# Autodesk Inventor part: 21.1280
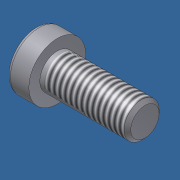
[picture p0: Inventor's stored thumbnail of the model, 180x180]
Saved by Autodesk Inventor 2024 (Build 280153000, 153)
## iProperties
Created: 2006-02
Part Number: 21.1280
Material: Steel, Mild
Description: M8X22 SHCS
Document SubType Name: Modeling
Standard: DIN 7984
Designer: Andy Moles
Standards Organization: DIN
Language: en-US
Size Designation: M8 x 20
Categories: <MemberInstance><Categories><Category DisplayName="Fasteners" InternalName="e4da775c-781d-43d5-af7c-5136215cf5a6" Mnemonic="FSTN"><Category DisplayName="Bolts"
Density: 7.85 g/cm^3
Mass: 13.0366 g
Surface Area: 10.6794 cm^2
Volume: 1.66071 cm^3
Vendor: S
Appearance: Zinc
Author: Andy Moles
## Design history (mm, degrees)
body "Solid1"
workplane "Work Plane1"
revolve "Body" stored, may be unused: angle "d10" = 90 deg
sketch "Sketch2"
  geometry: L1 (0, -7.8)-(0, 10.4) reference; L2 (-7.8, 0)-(10.4, 0) reference; L3 (2.887, 0)-(1.443, -2.5); L4 (1.443, -2.5)-(-1.443, -2.5); L5 (-1.443, -2.5)-(-2.887, 0); L6 (-2.887, 0)-(-1.443, 2.5); L7 (-1.443, 2.5)-(1.443, 2.5); L8 (1.443, 2.5)-(2.887, 0); 2 further points
  constraints: 12 end point, 1 coincident, 1 horizontal alignment, 1 point on line, 12 other
extrude "Slot" join sketch "Sketch2" stored distance "d11" = 10; taper "d12" = 0 deg
fillet "Fillet1" dims "d17" = 0.8 (= RR)
feature "Thread" dims "d13" = 22, "d14" = 0
chamfer "Chamfer1" distance "d15" = 0.76681 (= -0.5 x SPD + 0.5 x GD); stored, may be unused: second distance "d16" = 0.76681 (= GUL), angle "d27" = 45 deg
sketch "Sketch1"
  geometry: L1 (0.467, 0)-(22, 0); L2 (22, 0)-(22, 4); L3 (22, 4)-(1, 4); L4 (1, 4)-(0.233, 4); L5 (0.233, 4)-(0, 4); L6 (0, 4)-(0, 6.5); L7 (0, 6.5)-(-5, 6.5); L8 (-5, 6.5)-(-5, 2.887); L9 (-5, 2.887)-(-1.2, 2.887); L10 (-1.2, 2.887)-(0.467, 0); L11 (-7.5, 0)-(27.5, 0) reference; L12 (0, -0.65)-(0, 8.45) reference; L13 (1, 4)-(0, 4)
  constraints: 22 end point, 6 parallel, 2 collinear, 2 perpendicular, 1 horizontal, 1 point on line
  dimensions: "d1" = 21 distance from line of L3.end L2 (= GEL); "d2" = 0.76691 distance of L4.end L3.end (computed from GAL); "d3" = 5 distance between parallel lines of L8 L6 (= KOH); "d4" = 3.8 distance of L8.end L9.end (= INTI); "d5" = 60 deg angle of L10 L1; "d6" = 8 diameter of L3 L1 (= GD); "d7" = 8 diameter of L5 L1 (= BDM); "d8" = 5.7735 diameter of L9 L1 (= 1.1547 x SW); "d9" = 13 diameter of L7 L1 (= KOD); "d26" = 22 distance between parallel lines of L12 L2 (= NLG)
other parameters: "GD" = 8 (= NND) [user parameter; used in 2 equation terms], "NLG" = 22 [user parameter; used in 1 equation term], "GEL" = 21 [user parameter; used in 1 equation term], "KOD" = 13 [user parameter; used in 1 equation term], "KOH" = 5 [user parameter; used in 1 equation term], "INTI" = 3.8 [user parameter; used in 1 equation term], "GAL" = 0.76681 (= 0.61345 x PTC) [user parameter; used in 1 equation term], "GUL" = 0.76681 (= 0.61345 x PTC) [user parameter; used in 1 equation term], "BDM" = 8 (= NND) [user parameter; used in 1 equation term], "SW" = 5 [user parameter; used in 2 equation terms], "RR" = 0.8 [user parameter; used in 1 equation term], "SPD" = 6.46637 (= NND - 1.2269 x PTC) [user parameter; used in 1 equation term], "d19" = 0, "d28" = 0, "d29" = 0, "TOA" = 30 deg [user parameter], "GD1" = 6.46637 (= THREADDIA - 1.2269 x PTC) [user parameter], "THREADDIA" = 8 [user parameter; used in 1 equation term], "FAWI" = 45 deg [user parameter], "ANG" = 120 deg [user parameter], "TPU" = 8 (computed from PTC) [user parameter], "PTC" = 1.25 [user parameter; used in 5 equation terms], "NND" = 8 [user parameter; used in 3 equation terms], "E0" = 5.775 (= 1.155 x SW) [user parameter]
